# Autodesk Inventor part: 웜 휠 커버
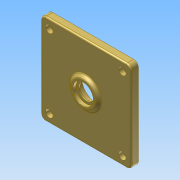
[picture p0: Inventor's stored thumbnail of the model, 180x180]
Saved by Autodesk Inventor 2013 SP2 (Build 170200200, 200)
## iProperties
Created: 2025-06
Part Number: 웜 휠 커버
Material: Generic
Document SubType Name: Modeling
Designer: a
Density: 1 g/cm^3
Author: a
변환 표준: STEP AP214IS
전처리기: Build: 200, Release: 2013 SP2 Update 6 - Date: Thu 07/17/2014
전송 단위: 밀리미터
불확실성: 0.01
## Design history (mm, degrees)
node "웜 휠 커버1"
node "솔리드1"
node "기준1"
